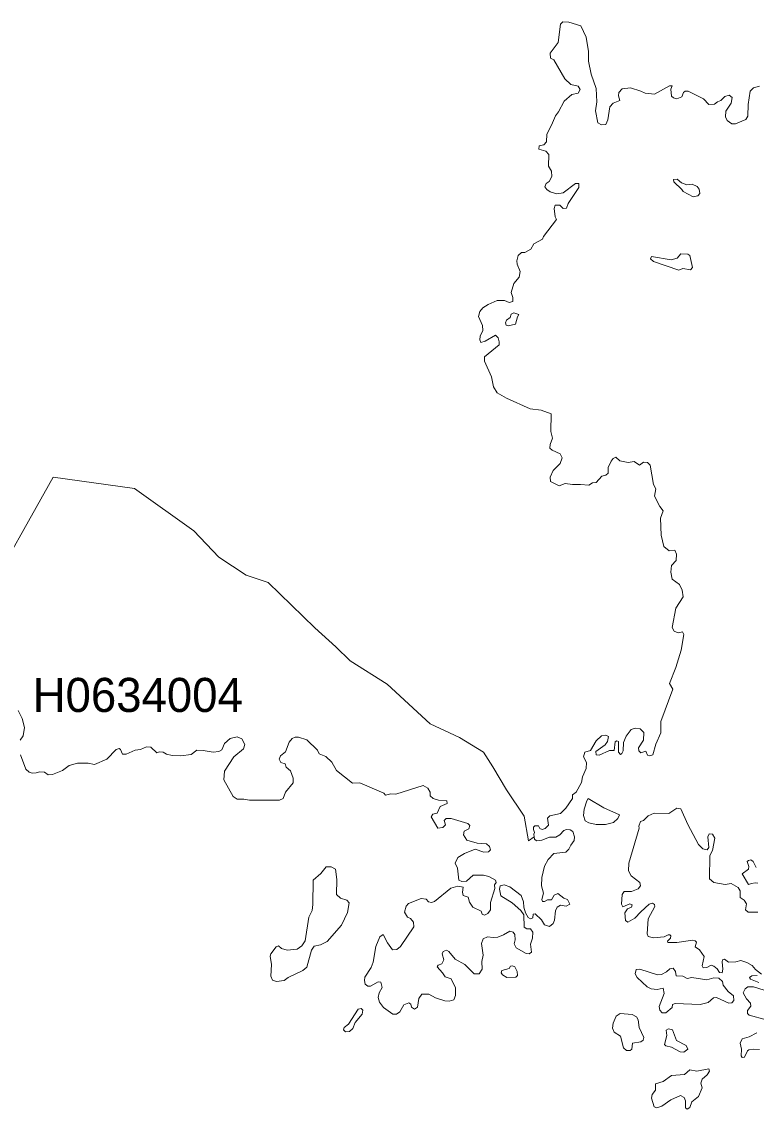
# Model space of a CAD drawing. Extents: x 369010 to 739155, y 6377141 to 6616555.
# Drawn here: x 455754 to 457911, y 6478805 to 6481997 of the extents above; entities that cross this region are included whole.
import ezdxf
from ezdxf.enums import TextEntityAlignment as Align

# ---------------------------------------------------------------- set-up
doc = ezdxf.new("R2010")
doc.units = 0
doc.header["$LTSCALE"] = 40
doc.layers.add('1', color=7, linetype='Continuous', lineweight=13)
doc.layers.add('2', color=7, linetype='Continuous')

msp = doc.modelspace()

# ---------------------------------------------------------------- linework, layer by layer
at = {"layer": '1'}
for points in [[(457100.21, 6481073.86), (457108.32, 6481090.9), (457107.16, 6481105.3), (457095.57, 6481131.29), (457099.87, 6481146.35), (457108.32, 6481157.11), (457123.87, 6481167.2), (457150.19, 6481178.12), (457171.37, 6481178.46), (457185.77, 6481172.99), (457195.87, 6481175.31), (457196.2, 6481187.39), (457191.23, 6481202.12), (457199.34, 6481228.44), (457214.73, 6481246.64), (457217.88, 6481264.02), (457208.61, 6481285.37), (457208.28, 6481294.97), (457211.76, 6481310.53), (457221.35, 6481319.47), (457231.45, 6481319.47), (457248.83, 6481329.06), (457258.1, 6481344.95), (457283.25, 6481358.52), (457286.4, 6481366.3), (457324.3, 6481416.62), (457320.82, 6481423.9), (457317.84, 6481448.39), (457320.82, 6481458.32), (457334.06, 6481458.32), (457344.49, 6481448.72), (457354.09, 6481449.05), (457359.22, 6481463.45), (457389.84, 6481509.96), (457389.84, 6481521.88), (457380.4, 6481521.88), (457344.49, 6481494.73), (457325.46, 6481491.75), (457305.76, 6481497.05), (457295.67, 6481504), (457290.7, 6481512.28), (457294.34, 6481521.88), (457303.28, 6481527.34), (457311.06, 6481542.73), (457310.23, 6481557.96), (457300.96, 6481573.02), (457302.12, 6481606.61), (457293.68, 6481616.71), (457272.5, 6481622.5), (457273.32, 6481632.6), (457287.56, 6481634.92), (457294.84, 6481643.85), (457295.83, 6481666.36), (457310.23, 6481692.68), (457321.48, 6481720.48), (457330.75, 6481732.07), (457346.97, 6481763.51), (457369.32, 6481782.88), (457387.85, 6481786.68), (457394.47, 6481797.94), (457387.85, 6481807.21), (457367, 6481812.67), (457349.12, 6481828.56), (457316.52, 6481884.66), (457306.59, 6481890.12), (457306.09, 6481904.36), (457329.59, 6481935.8), (457336.21, 6481989.26), (457343.5, 6481996.54), (457360.54, 6481995.05), (457396.46, 6481984.96), (457411.19, 6481951.19), (457418.14, 6481909.49), (457418.14, 6481880.85), (457426.41, 6481842.46), (457441.47, 6481801.08), (457442.96, 6481761.86), (457439.49, 6481734.88), (457446.11, 6481699.96), (457456.54, 6481693.84), (457468.95, 6481694.99), (457475.57, 6481708.9), (457481.36, 6481746.8), (457490.63, 6481757.72), (457510.16, 6481765.83), (457506.35, 6481779.4), (457507.84, 6481789.33), (457517.11, 6481799.92), (457541.44, 6481802.24), (457572.55, 6481793.3), (457584.47, 6481787.01), (457612.27, 6481783.54), (457655.97, 6481808.36), (457664.08, 6481808.03), (457660.6, 6481798.76), (457661.76, 6481777.75), (457667.88, 6481773.61), (457677.65, 6481770.13), (457692.71, 6481775.93), (457697.67, 6481789)], [(457697.67, 6481789), (457702.31, 6481792.97), (457710.92, 6481793.3), (457755.93, 6481770.46), (457772.15, 6481753.75), (457788.87, 6481754.24), (457796.98, 6481761.86), (457807.07, 6481765.33), (457818.99, 6481777.08), (457831.4, 6481781.22), (457840.01, 6481774.27), (457837.69, 6481758.05), (457821.31, 6481733.72), (457820.98, 6481717.83), (457825.61, 6481706.25), (457839.51, 6481697.31), (457850.6, 6481696.81), (457880.39, 6481709.72), (457886.68, 6481719.32), (457887.01, 6481753.75), (457893.14, 6481793.3), (457903.23, 6481802.24), (457920.28, 6481807.54)], [(457501.39, 6479886.53), (457506.85, 6479883.88), (457506.85, 6479853.27), (457512.64, 6479846.31), (457516.12, 6479848.63), (457520.25, 6479856.41), (457521.74, 6479881.07), (457529.19, 6479899.77), (457543.43, 6479919.47), (457555.51, 6479922.94), (457569.74, 6479921.78), (457580.66, 6479910.53), (457580.17, 6479888.52), (457565.44, 6479865.18), (457565.93, 6479856.41), (457572.39, 6479851.28), (457586.46, 6479855.58), (457591.75, 6479844.33), (457598.7, 6479841.68), (457607.48, 6479845.16), (457616.41, 6479876.1), (457630.81, 6479909.87), (457631.14, 6479943.13), (457666.23, 6480037.97), (457656.46, 6480054.19), (457675, 6480101.02), (457690.39, 6480151.83), (457698.5, 6480198.67), (457694.53, 6480206.29), (457682.28, 6480202.81), (457670.53, 6480208.27), (457664.08, 6480219.19), (457674.67, 6480275.3), (457696.02, 6480308.9), (457694.03, 6480328.26), (457685.43, 6480344.98), (457664.57, 6480360.87), (457660.27, 6480380.89), (457661.76, 6480400.75), (457675.99, 6480414.99), (457677.15, 6480434.02), (457672.19, 6480445.6), (457655.47, 6480444.11), (457640.08, 6480456.86), (457631.64, 6480490.12), (457629.82, 6480540.11), (457637.43, 6480560.96), (457628.16, 6480573.7), (457611.94, 6480604.32), (457616.58, 6480625.67), (457609.63, 6480638.42), (457600.03, 6480695.35), (457591.75, 6480702.63), (457580.17, 6480703.79), (457568.09, 6480695.35), (457552.86, 6480706.11), (457534.65, 6480703.13), (457510.32, 6480707.76), (457498.41, 6480718.52), (457490.46, 6480714.71), (457485, 6480706.93), (457476.07, 6480687.9), (457476.56, 6480672.01), (457469.44, 6480665.89), (457457.53, 6480662.75), (457441.31, 6480644.54), (457430.39, 6480643.05), (457419.96, 6480636.43), (457395.13, 6480638.75), (457371.96, 6480638.42), (457349.95, 6480641.56), (457332.08, 6480634.94), (457307.25, 6480647.68), (457305.76, 6480660.1), (457315.03, 6480679.79), (457335.55, 6480700.31), (457340.68, 6480716.53), (457335.55, 6480728.62), (457311.89, 6480739.37), (457305.43, 6480745.33), (457306.09, 6480755.76), (457312.38, 6480773.96), (457307.75, 6480794.49), (457308.91, 6480845.96), (457279.78, 6480856.38), (457247.34, 6480861.02), (457177.33, 6480891.97), (457149.86, 6480907.03), (457139.76, 6480925.23), (457133.97, 6480954.36), (457113.45, 6481000.7), (457112.95, 6481012.79), (457155.98, 6481048.37), (457156.31, 6481056.98), (457153.66, 6481068.56), (457145.55, 6481076.67), (457115.27, 6481059.29), (457102.52, 6481055.32), (457099.05, 6481062.77), (457100.21, 6481073.86)], [(455637.32, 6480288.04), (455846.84, 6480659.6), (456085.34, 6480627.16), (456259.61, 6480502.54), (456333.26, 6480425.58), (456413.2, 6480372.29), (456477.74, 6480351.1), (456615.28, 6480217.87), (456677.01, 6480161.6), (456719.05, 6480120.89), (456827.45, 6480052.86), (456953.24, 6479936.02), (457039.3, 6479896.13), (457109.97, 6479853.1), (457137.61, 6479810.07), (457177.5, 6479742.54), (457229.8, 6479665.58), (457242.54, 6479592.43), (457259.09, 6479604.84), (457258.43, 6479612.13), (457260.25, 6479617.42), (457256.77, 6479626.36), (457256.77, 6479632.98), (457261.08, 6479636.46), (457271.34, 6479636.46), (457275.64, 6479628.68), (457282.92, 6479626.03), (457291.53, 6479629.17), (457301.46, 6479639.1), (457297.65, 6479659.29), (457304.93, 6479666.25), (457336.38, 6479673.2), (457351.77, 6479688.26), (457371.14, 6479717.39), (457371.14, 6479727.81), (457382.39, 6479735.26), (457397.45, 6479764.22), (457400.93, 6479780.94), (457411.68, 6479804.94), (457412.84, 6479822.32), (457403.91, 6479839.36), (457407.71, 6479853.27), (457424.1, 6479858.23), (457440.98, 6479886.53), (457456.54, 6479900.93), (457469.78, 6479903.25), (457477.06, 6479898.94), (457474.74, 6479884.55), (457467.79, 6479874.62), (457440.32, 6479854.75), (457440.98, 6479845.49), (457449.92, 6479844.33), (457479.71, 6479858.23), (457494.11, 6479857.9), (457496.75, 6479883.06), (457501.39, 6479886.53)], [(455846.84, 6480659.6), (455637.32, 6480288.04)], [(457109.31, 6479257.45), (457104.01, 6479291.88), (457109.31, 6479305.12), (457122.22, 6479310.91), (457138.44, 6479309.25), (457152.34, 6479310.41), (457168.89, 6479316.7), (457187.1, 6479327.96), (457197.69, 6479325.14), (457202.65, 6479317.86), (457203.48, 6479302.3), (457200, 6479290.72), (457206.13, 6479279.13), (457235.09, 6479262.08), (457244.03, 6479260.6), (457250.65, 6479265.89), (457248.33, 6479289.89), (457254.12, 6479306.61), (457255.12, 6479325.14), (457248.17, 6479334.08), (457237.24, 6479334.08), (457229.46, 6479339.54), (457228.31, 6479375.95), (457219.86, 6479388.36), (457194.38, 6479410.71), (457160.95, 6479431.23), (457156.81, 6479450.59), (457158.63, 6479460.69), (457171.04, 6479463.83), (457187.26, 6479457.55), (457220.69, 6479432.06), (457227.97, 6479413.52), (457228.31, 6479397.63), (457233.93, 6479380.92), (457241.38, 6479367.35), (457248.66, 6479363.87), (457254.95, 6479366.68), (457256.11, 6479377.77), (457261.9, 6479378.6), (457280.77, 6479360.39), (457289.71, 6479346.16), (457304.44, 6479341.53), (457315.2, 6479349.64), (457318.84, 6479359.57), (457321.15, 6479387.54), (457326.61, 6479398.29), (457336.05, 6479403.43), (457352.93, 6479401.11), (457363.85, 6479406.9), (457357.23, 6479420.8), (457345.65, 6479424.28), (457328.27, 6479438.18), (457317.84, 6479433.22), (457309.57, 6479419.98), (457297.65, 6479419.64), (457289.21, 6479414.18), (457283.75, 6479414.18), (457281.43, 6479420.8), (457286.73, 6479438.68), (457280.27, 6479461.02), (457281.43, 6479484.69), (457289.71, 6479518.78), (457299.8, 6479538.15), (457316.35, 6479555.19), (457351.61, 6479559.5), (457360.87, 6479567.94), (457366.83, 6479580.35), (457376.1, 6479593.92), (457377.26, 6479604.35), (457372.63, 6479619.74), (457364.85, 6479624.54), (457353.59, 6479626.03), (457345.81, 6479622.55), (457334.23, 6479610.14), (457322.97, 6479603.52), (457304.44, 6479603.52), (457281.27, 6479594.25), (457265.71, 6479593.09), (457259.92, 6479597.73), (457259.09, 6479604.84), (457242.54, 6479592.43), (457229.8, 6479665.58), (457177.5, 6479742.54), (457137.61, 6479810.07), (457109.97, 6479853.1), (457039.3, 6479896.13), (456953.24, 6479936.02), (456827.45, 6480052.86), (456719.05, 6480120.89), (456677.01, 6480161.6), (456615.28, 6480217.87), (456477.74, 6480351.1), (456413.2, 6480372.29), (456333.26, 6480425.58), (456259.61, 6480502.54), (456085.34, 6480627.16), (455846.84, 6480659.6)], [(455743.24, 6479974.75), (455754.99, 6479952.07), (455762.27, 6479925.59), (455758.8, 6479900.76), (455749.69, 6479888.19)], [(455821.03, 6479794.18), (455831.78, 6479786.24), (455844.86, 6479786.9), (455873.49, 6479799.15), (455893.02, 6479813.38), (455918.01, 6479820.99), (455948.79, 6479820.66), (455968.32, 6479816.52), (456003.91, 6479832.25), (456031.88, 6479861.21), (456040.48, 6479863.2), (456043.79, 6479860.88), (456050.58, 6479847.47), (456061.17, 6479846.81), (456086.99, 6479859.06), (456102.71, 6479860.55), (456120.92, 6479868.33), (456133, 6479867.66), (456150.71, 6479850.62), (456158.16, 6479853.6), (456169.25, 6479853.27), (456178.84, 6479847.47), (456196.22, 6479843.17), (456221.05, 6479842.51), (456251.5, 6479846.31), (456268.22, 6479858.73), (456287.25, 6479858.23), (456315.88, 6479852.93), (456333.26, 6479854.42), (456342.03, 6479859.39), (456349.64, 6479878.42), (456366.36, 6479892.82), (456386.88, 6479897.45), (456400.79, 6479891.99), (456409.72, 6479875.77), (456405.42, 6479863.03), (456376.79, 6479839.03), (456349.64, 6479796.83), (456347.99, 6479772), (456375.46, 6479722.35), (456387.05, 6479715.07), (456406.74, 6479715.07), (456422.8, 6479711.59), (456510.68, 6479712.42), (456521.93, 6479717.06), (456528.72, 6479735.59), (456551.56, 6479762.73), (456551.56, 6479776.97), (456543.45, 6479797.99), (456530.21, 6479808.74), (456527.56, 6479818.51), (456515.48, 6479822.65), (456510.18, 6479831.92), (456513.66, 6479841.68), (456529.22, 6479853.6), (456539.81, 6479882.23), (456548.25, 6479893.48), (456556.69, 6479896.96), (456566.46, 6479896.96), (456591.28, 6479888.85), (456622.56, 6479858.73), (456627.69, 6479847.8), (456647.22, 6479840.52), (456664.93, 6479823.81), (456678.83, 6479798.65), (456725.34, 6479762.24), (456746.69, 6479763.07), (456817.36, 6479732.45), (456822.66, 6479726.32), (456837.88, 6479730.46), (456852.45, 6479729.8), (456932.72, 6479754.62), (456946.62, 6479747.18), (456953.24, 6479735.92), (456953.9, 6479724.67), (456962.51, 6479716.56), (456977.73, 6479712.42), (457002.89, 6479710.44), (457003.72, 6479702.66), (456983.19, 6479693.06), (456973.93, 6479673.69), (456961.51, 6479670.55), (456956.05, 6479663.1), (456975.75, 6479629.83), (456990.97, 6479632.15), (456998.59, 6479639.93), (456995.11, 6479652.34), (457000.24, 6479658.14), (457015.3, 6479657.81), (457064.13, 6479643.9), (457069.92, 6479637.28), (457067.1, 6479628.35), (457053.53, 6479621.39), (457051.22, 6479610.47), (457061.31, 6479594.25), (457091.93, 6479585.81), (457119.4, 6479583.49), (457127.51, 6479575.72), (457130.66, 6479566.78), (457125.2, 6479560.65)], [(455750.85, 6479845.16), (455766.41, 6479803.12), (455775.84, 6479794.68), (455784.61, 6479791.2), (455796.2, 6479791.86), (455807.29, 6479795.01), (455821.03, 6479794.18)], [(457915.64, 6479383.23), (457887.84, 6479382.9), (457879.23, 6479389.85), (457882.21, 6479408.06), (457875.26, 6479418.49), (457864.34, 6479426.26), (457863.51, 6479445.63), (457858.21, 6479456.06), (457837.19, 6479467.31), (457820.15, 6479464.99), (457786.55, 6479470.45), (457774.14, 6479481.54), (457775.13, 6479549.4), (457782.41, 6479564.46), (457789.53, 6479600.87), (457782.91, 6479612.13), (457772.81, 6479613.62), (457769.01, 6479604.35), (457771.66, 6479572.9), (457766.69, 6479565.95), (457754.28, 6479568.76), (457741.53, 6479581.84), (457710.42, 6479640.76), (457689.73, 6479686.44), (457677.81, 6479688.75), (457654.48, 6479672.87), (457611.61, 6479674.02), (457593.74, 6479665.91), (457580.17, 6479652.01), (457571.4, 6479649.2), (457565.93, 6479635.3), (457567.09, 6479630.33), (457536.47, 6479527.39), (457535.48, 6479504.55), (457544.09, 6479490.15), (457569.24, 6479470.45), (457571.23, 6479460.69), (457564.61, 6479451.42), (457544.75, 6479443.64), (457523.07, 6479443.64), (457517.77, 6479435.2), (457515.79, 6479406.9), (457519.26, 6479398.79), (457539.45, 6479408.06), (457546.74, 6479404.58), (457544.42, 6479397.96), (457533.16, 6479393), (457525.55, 6479380.92), (457526.71, 6479358.9), (457534.32, 6479354.27), (457554.51, 6479365.86), (457571.89, 6479384.06), (457596.72, 6479406.9), (457606.65, 6479410.05), (457611.94, 6479406.07), (457613.6, 6479399.95), (457593.74, 6479363.54), (457590.76, 6479319.35), (457593.41, 6479312.4), (457609.63, 6479308.26), (457641.07, 6479311.24), (457652.33, 6479317.03), (457657.29, 6479317.03), (457659.94, 6479313.56), (457659.61, 6479307.1), (457650.67, 6479298.5)], [(457125.2, 6479560.65), (457111.63, 6479559), (457085.81, 6479567.94), (457054.36, 6479555.85), (457035, 6479544.27), (457026.56, 6479527.22), (457033.51, 6479512.16), (457037.31, 6479477.41), (457046.25, 6479473.1), (457060.65, 6479474.59), (457080.01, 6479491.64), (457109.8, 6479491.64), (457126.02, 6479488.49), (457145.72, 6479477.41), (457147.71, 6479470.79), (457142.24, 6479463.83), (457143.07, 6479452.58), (457130.66, 6479411.54), (457130.33, 6479390.68), (457123.21, 6479379.43), (457113.28, 6479374.3), (457106.66, 6479377.44), (457103.52, 6479386.38), (457078.36, 6479398.29), (457068.76, 6479412.36), (457064.79, 6479427.09), (457050.89, 6479432.39), (457048.24, 6479442.15), (457050.89, 6479456.39), (457035, 6479459.86), (457013.81, 6479453.74), (456966.15, 6479414.68), (456957.54, 6479411.87), (456948.27, 6479413.52), (456941.32, 6479421.13), (456927.09, 6479423.12), (456890.35, 6479409.22), (456882.9, 6479400.61), (456878.6, 6479382.9), (456886.71, 6479369), (456896.14, 6479364.37), (456904.41, 6479353.77), (456905.57, 6479340.37), (456866.51, 6479282.61), (456856.09, 6479273.34), (456843.18, 6479272.51), (456828.12, 6479293.37), (456815.7, 6479317.86), (456805.28, 6479310.91), (456794.02, 6479282.28), (456786.58, 6479236.93), (456780.29, 6479221.04), (456761.42, 6479192.74), (456760.26, 6479182.64), (456762.91, 6479171.89), (456770.36, 6479166.42), (456778.47, 6479166.42), (456801.31, 6479178.84), (456808.26, 6479178.01), (456812.89, 6479162.62), (456803.62, 6479146.4), (456801.31, 6479132.83), (456804.78, 6479119.26), (456816.04, 6479103.7), (456844.34, 6479084.33), (456854.93, 6479084.33), (456864.2, 6479091.28), (456876.61, 6479111.48), (456890.51, 6479116.94), (456896.3, 6479112.97), (456898.62, 6479104.19), (456907.56, 6479099.06), (456916.33, 6479104.86), (456919.97, 6479130.01), (456929.57, 6479142.92), (456949.27, 6479142.92), (456969.62, 6479132), (456997.1, 6479123.06), (457009.51, 6479121.9), (457022.58, 6479126.54), (457028.05, 6479138.62), (457027.71, 6479160.96), (457015.63, 6479187.77), (456997.43, 6479193.24), (456990.15, 6479205.48), (456973.93, 6479222.53), (456976.57, 6479227.99), (456988.16, 6479231.8), (456993.95, 6479243.55), (456988.66, 6479260.93), (456992.13, 6479267.88), (457001.73, 6479271.35), (457008.35, 6479267.55), (457026.56, 6479245.87), (457055.19, 6479229.48), (457082.99, 6479202.01), (457097.39, 6479202.01), (457105.83, 6479216.07), (457105.5, 6479238.91), (457109.31, 6479257.45)], [(457911.18, 6479514.15), (457902.24, 6479531.86), (457895.62, 6479536.66), (457888, 6479535), (457884.03, 6479531.86), (457889.16, 6479517.29), (457888.34, 6479509.84), (457869.96, 6479495.94), (457888.5, 6479464.17), (457897.11, 6479467.64), (457908.2, 6479469.3), (457915.97, 6479468.14)], [(457650.67, 6479298.5), (457651.5, 6479293.86), (457677.81, 6479294.69), (457724.98, 6479301.31), (457731.44, 6479298.99), (457735.24, 6479295.02), (457732.1, 6479281.95), (457744.18, 6479272.68), (457757.75, 6479253.31), (457751.96, 6479225.84), (457755.44, 6479219.55), (457766.19, 6479220.71), (457778.61, 6479227.66), (457786.72, 6479225.01), (457796.48, 6479216.9), (457803.27, 6479205.98), (457810.55, 6479205.65), (457813.2, 6479215.74), (457811.38, 6479237.76), (457812.04, 6479243.88), (457817.83, 6479245.53), (457829.91, 6479236.27), (457851.59, 6479237.76), (457865.5, 6479241.56), (457883.37, 6479235.77), (457898.76, 6479226.83), (457908.86, 6479215.25), (457926.07, 6479201.68)], [(457914.15, 6479197.54), (457898.6, 6479196.38), (457891.65, 6479191.75), (457893.96, 6479186.28), (457918.79, 6479177.35)], [(457934.68, 6479154.18), (457903.23, 6479164.11), (457886.18, 6479164.6), (457878.07, 6479158.81), (457872.61, 6479146.73), (457882.05, 6479129.02), (457894.29, 6479116.11), (457894.79, 6479107.34), (457885.52, 6479094.93), (457885.52, 6479085.99), (457890.32, 6479081.35), (457940.14, 6479067.45)], [(457912.33, 6479029.55), (457890.32, 6479017.14), (457869.8, 6479011.68), (457863.51, 6478998.44), (457867.81, 6478981.06), (457866.32, 6478961.36), (457869.8, 6478956.73), (457876.42, 6478958.22), (457885.52, 6478976.43), (457889, 6478979.07), (457902.4, 6478981.39), (457920.28, 6478980.73)]]:
    msp.add_lwpolyline(points, dxfattribs=at)
for points in [[(457725.98, 6481482.49), (457739.22, 6481485.47), (457745.34, 6481492.58), (457743.85, 6481505), (457737.4, 6481513.27), (457722.5, 6481519.89), (457706.94, 6481518.24), (457691.39, 6481524.19), (457679.14, 6481534.62), (457668.55, 6481533.79), (457669.37, 6481526.84), (457692.88, 6481504.66), (457696.02, 6481498.21)], [(457717.87, 6481268.66), (457724.32, 6481274.94), (457716.21, 6481310.36), (457709.92, 6481314.5), (457689.57, 6481315.33), (457678.81, 6481302.75), (457660.93, 6481297.78), (457603.34, 6481307.22), (457600.19, 6481300.6), (457609.13, 6481292.82), (457683.28, 6481267.66), (457695.03, 6481272.13)], [(457199.01, 6481142.54), (457191.23, 6481138.57), (457188.09, 6481128.14), (457177.66, 6481121.19), (457175.01, 6481112.59), (457176.83, 6481106.46), (457182.3, 6481104.48), (457204.31, 6481108.78), (457209.77, 6481130.79), (457214.4, 6481137.08)], [(457417.81, 6479717.06), (457413.17, 6479710.44), (457405.89, 6479685.28), (457404.24, 6479667.07), (457408.87, 6479651.52), (457419.46, 6479645.72), (457440.65, 6479641.09), (457468.12, 6479640.76), (457491.79, 6479646.88), (457505.03, 6479658.47), (457509.17, 6479668.56), (457463.98, 6479689.09)], [(456648.38, 6479516.13), (456632.66, 6479496.77), (456609.65, 6479476.91), (456609.16, 6479406.07), (456606.84, 6479388.7), (456597.74, 6479368.5), (456586.65, 6479299.65), (456576.55, 6479284.59), (456563.31, 6479274.5), (456533.19, 6479272.18), (456516.97, 6479276.81), (456508.36, 6479284.59), (456501.08, 6479281.78), (456486.02, 6479260.6), (456483.54, 6479253.98), (456487.68, 6479229.98), (456485.36, 6479195.55), (456490.32, 6479183.47), (456502.07, 6479179.66), (456524.42, 6479182.81), (456536.5, 6479192.08), (456579.86, 6479211.77), (456591.45, 6479221.87), (456605.35, 6479271.35), (456612.47, 6479283.43), (456631.83, 6479287.24), (456650.86, 6479297.34), (456692.73, 6479345), (456710.44, 6479382.57), (456715.24, 6479410.71), (456709.12, 6479418.49), (456690.58, 6479424.78), (456678.17, 6479435.2), (456679, 6479479.23), (456675.52, 6479509.84), (456663.11, 6479516.13)], [(457204.97, 6479192.41), (457209.93, 6479197.87), (457208.78, 6479208.96), (457201.82, 6479223.36), (457195.7, 6479226.01), (457189.41, 6479224.85), (457185.61, 6479218.39), (457164.26, 6479212.1), (457162.44, 6479205.15), (457165.91, 6479199.03), (457178.99, 6479192.08)], [(457666.89, 6479218.72), (457657.46, 6479216.9), (457647.86, 6479207.97), (457632.63, 6479200.68), (457621.38, 6479199.86), (457569.24, 6479215.74), (457558.82, 6479214.92), (457556, 6479202.5), (457561.13, 6479191.75), (457590.43, 6479163.78), (457602.34, 6479157.98), (457620.05, 6479156.82), (457637.6, 6479160.8), (457640.25, 6479144.41), (457626.34, 6479106.84), (457627.83, 6479095.75), (457634.78, 6479088.31), (457645.71, 6479087.97), (457664.24, 6479103.37), (457665.07, 6479111.97), (457673.18, 6479115.78), (457746.5, 6479112.3), (457769.67, 6479118.1), (457785.89, 6479131.67), (457794.83, 6479132.83), (457830.41, 6479116.28), (457839.84, 6479116.94), (457845.14, 6479123.89), (457843.98, 6479138.29), (457828.59, 6479150.7), (457814.19, 6479169.57), (457811.54, 6479179.66), (457800.95, 6479189.76), (457786.22, 6479190.92), (457766.36, 6479184.3), (457722.34, 6479192.08), (457708.43, 6479188.93), (457695.19, 6479195.88), (457675.5, 6479196.71), (457673.51, 6479209.12)], [(456750.66, 6479100.72), (456741.89, 6479098.73), (456713.59, 6479054.21), (456700.84, 6479045.27), (456699.19, 6479037.99), (456704.98, 6479032.53), (456716.73, 6479032.86), (456726, 6479041.47), (456733.78, 6479059.18), (456753.47, 6479084.33), (456756.12, 6479095.59)], [(457530.35, 6478976.92), (457541.11, 6478977.58), (457545.41, 6478981.06), (457547.73, 6478999.26), (457572.06, 6479002.41), (457579.01, 6479007.87), (457580.99, 6479015.48), (457567.09, 6479044.94), (457564.44, 6479067.45), (457559.31, 6479075.89), (457546.24, 6479082.84), (457511.65, 6479085.99), (457500.06, 6479077.88), (457490.79, 6479057.36), (457489.31, 6479042.63), (457494.27, 6479031.04), (457512.14, 6479019.79), (457521.74, 6478985.03)], [(457698.5, 6478972.12), (457710.42, 6478981.06), (457705.45, 6478991.98), (457676.49, 6479007.04), (457665.24, 6479038.32), (457653.15, 6479040.64), (457647.03, 6479037.17), (457648.52, 6479021.44), (457641.24, 6478995.46), (457645.54, 6478991.15), (457662.42, 6478986.85), (457687.25, 6478973.78)], [(457771.82, 6478923.79), (457736.73, 6478916.51), (457716.21, 6478920.32), (457699.99, 6478906.75), (457661.76, 6478904.1), (457638.09, 6478886.23), (457615.58, 6478879.27), (457614.92, 6478861.07), (457605.65, 6478848.32), (457603.34, 6478837.4), (457611.78, 6478812.25), (457619.06, 6478809.27), (457633.46, 6478813.9), (457659.94, 6478832.11), (457689.07, 6478844.85), (457699, 6478839.06), (457703.8, 6478829.79), (457703.3, 6478809.27), (457707.94, 6478804.96), (457715.71, 6478810.42), (457722.34, 6478826.31), (457741.2, 6478842.53), (457752.13, 6478867.69), (457748.65, 6478881.59), (457752.13, 6478892.85), (457767.19, 6478905.59), (457773.81, 6478916.84)]]:
    msp.add_lwpolyline(points, close=True, dxfattribs=at)

# ---------------------------------------------------------------- texts
at = {"layer": '2'}
msp.add_text('H0634004', height=100, dxfattribs=at).set_placement((456094.9, 6479970.94), align=Align.CENTER)

doc.saveas('drawing.dxf')
